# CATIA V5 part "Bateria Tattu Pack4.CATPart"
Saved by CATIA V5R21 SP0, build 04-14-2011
Part number: Bateria Tattu Pack4
Material "DS Red": density 7860 kg/m3, Young's modulus 2e+11 Pa, Poisson ratio 0.266
Bounding box of the stored display mesh (mm): x 34.5 to 386.5, y 0 to 111.5, z -48 to 48
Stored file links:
  C:\Users\rodri\OneDrive\Área de Trabalho\Bateria Tattu Pack4.CATPart
  C:\Program Files (x86)\Dassault Systemes\B21\intel_a\startup\materials\red_env_512x512.jpg
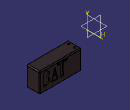
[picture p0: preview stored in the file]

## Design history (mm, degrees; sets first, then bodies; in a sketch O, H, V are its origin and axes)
Body1 (main body), material "DS Red"
  Sketch1 on yz-plane, origin (0, 0, 0), H (0, 1, 0), V (0, 0, 1)
    line L1 (-106.5, 48) -> (106.5, 48)
    line L2 (106.5, 48) -> (106.5, -48)
    line L3 (106.5, -48) -> (-106.5, -48)
    line L4 (-106.5, -48) -> (-106.5, 48)
    distance L4 L2 = 213
    distance L3 L1 = 96
    horizontal: L1 H, L3 H
    vertical: L2 V, L4 V
    symmetry: L4 L2 V, L3 L1 H
  Pad1: profile Sketch1, direction (1, 0, 0), length 34.5, mirrored extent
  Fillet1: radius 5, on edge [face of Pad1 from Sketch1.L1 | face of Pad1 from Sketch1.L2]
  Fillet2: radius 5, on edge [face of Pad1 from Sketch1.L2 | end face of Pad1]; edge [face of Pad1 from Sketch1.L1 | end face of Pad1]; edge [start face of Pad1 | face of Pad1 from Sketch1.L1]; edge [face of Pad1 from Sketch1.L4 | face of Pad1 from Sketch1.L1]; edge [face of Pad1 from Sketch1.L4 | end face of Pad1]; edge [start face of Pad1 | face of Pad1 from Sketch1.L2]
  Fillet3: radius 5, on edge [start face of Pad1 | face of Pad1 from Sketch1.L4]
  Sketch2 on face of Pad1 from Sketch1.L1, origin (0, 0, 48), H (1, 0, 0), V (0, 1, 0)
    circle A1 centre (-14.5, -90) radius 5
    point P1 (-14.5, -90)
    circle A2 centre (14.5, -90) radius 5
    point P2 (14.5, -90)
    reference projected line E1 (-34.5, 101.5) -> (-34.5, -106.5) from edge [start face of Pad1 | face of Fillet2]
    distance P1 E1 = 20
    radius A1 = 5
    radius A2 = 5
    distance A2 H = 85
    symmetry: P1 P2 V
  Pocket1: profile Sketch2, direction (0, 0, -1), length 10
  Sketch3 on start face of Pad1, origin (-34.5, 0, 0), H (0, -1, 0), V (0, 0, 1)
    line L1 (-86.2435, -27.0111) -> (-86.2435, 30.4896)
    arc A1 centre (-73.5977, 21.6671) radius 15.4193 from (-86.2435, 30.4896) to (-68.3938, 7.1525) cw
    arc A2 centre (-74.0974, -9.6616) radius 17.7552 from (-68.3938, 7.1525) to (-70.3235, -27.0111) cw
    line L2 (-70.3235, -27.0111) -> (-86.2435, -27.0111)
    point P7 (-46.9259, -27.0111)
    line L3 (-46.9259, -27.0111) -> (-30.0411, 30.4896)
    line L4 (-30.0411, 30.4896) -> (-13.3975, -27.0111)
    point P9 (-13.3975, -27.0111)
    line L5 (-13.3975, -27.0111) -> (-46.9259, -27.0111)
    point P10 (-37.5187, 0)
    line L6 (-37.5187, 0) -> (-23.046, 0)
    line L7 (-23.046, 0) -> (-23.046, -5.3581)
    line L8 (-23.046, -5.3581) -> (-37.5187, -5.3581)
    line L9 (-37.5187, -5.3581) -> (-37.5187, 0)
    point P14 (0, 30.4896)
    line L10 (0, 30.4896) -> (0, -27.0111)
    point P15 (0, -27.0111)
    line L11 (0, -27.0111) -> (14.58, -26.9312)
    line L12 (14.58, -26.9312) -> (14.2654, 30.4896)
    line L13 (14.2654, 30.4896) -> (32.674, 30.4896)
    line L14 (32.674, 30.4896) -> (32.674, 40.1131)
    line L15 (32.674, 40.1131) -> (-15.086, 40.1131)
    line L16 (-15.086, 40.1131) -> (-15.086, 30.4896)
    point P21 (-15.086, 30.4896)
    line L17 (-15.086, 30.4896) -> (0, 30.4896)
    vertical: L1 V, L7 V, L9 V, L10 V, L14 V, L16 V
    horizontal: L2 H, L5 H, L6 H, L8 H, L13 H, L15 H, L17 H
    coincidence: P7 L2, P9 L2, P10 H, P14 V, P15 L2, P21 L13
    tangency: L11 A2
  Pocket2: profile Sketch3, direction (1, 0, 0), length 5
  Sketch4 on end face of Pad1, origin (34.5, 0, 0), H (0, 1, 0), V (0, 0, 1)
    axis line L1 (-201.212, 0) -> (227.9274, 0)
    point P1 (-201.212, 0)
    coincidence: P1 H
    horizontal: L1 H
  Rotate1: ToTransfor Pocket2, Angle 90, Axis edge [start face of Pad1 | face of Fillet2]
  Rotate2: ToTransfor Rotate1, Angle 90, Axis edge [face of Pad1 from Sketch1.L4 | face of Fillet3]
  Rotate3: ToTransfor Rotate2, Angle 90, Axis edge [face of Pad1 from Sketch1.L4 | face of Fillet3]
